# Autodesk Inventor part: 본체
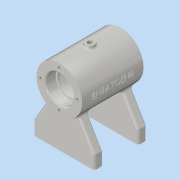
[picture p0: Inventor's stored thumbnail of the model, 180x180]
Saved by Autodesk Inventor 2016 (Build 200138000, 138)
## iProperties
Created: 2018-05
Part Number: 본체
Material: 알루미늄 6061
Document SubType Name: Modeling
Designer: 605-17
Density: 2.7 g/cm^3
Appearance: 알루미늄 - 평지
Mass: 317.791 g
Surface Area: 375.834 cm^2
Volume: 117.701 cm^3
Author: 605-17
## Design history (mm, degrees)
sketch "스케치1"
  geometry: C1 r 26 at (0, 65); 1 further point
  constraints: 1 centre point, 1 vertical alignment
  dimensions: "d0" = 52 diameter of C1; "d1" = 65 distance of point (0, 0) C1.centre
extrude "돌출1" new body sketch "스케치1" stored distance "d2" = 70; taper "d3" = 0 deg
node "작업 평면1"
sketch "스케치3"
  geometry: L1 (-35, 0)-(35, 0); L2 (-35, 0)-(-35, 15); L3 (-35, 15)-(-16.058, 47.808); L4 (-16.058, 47.808)-(16.058, 47.808); L5 (35, 0)-(35, 15); L6 (35, 15)-(16.058, 47.808); 2 further points
  constraints: 12 end point, 2 horizontal, 2 vertical, 1 coincident, 1 midpoint
  dimensions: "d5" = 70 distance of L1.start L1.end; "d6" = 15 distance of L1.start L2.end; "d7" = 30 deg angle of L2 L3; "d8" = 15 distance of L1.end L5.end; "d9" = 30 deg angle of L5 L6; "d10" = 32.11665 distance of L3.end L4.end
extrude "돌출2" join sketch "스케치3" distance "d11" = 10; taper "d12" = 0 deg
sketch "스케치4"
  geometry: L1 (81, 35)-(65, 35); L2 (65, 35)-(65, 23); L3 (65, 23)-(81, 23); L4 (81, 23)-(81, 35); L5 (79, 23)-(65, 23); L6 (65, 23)-(65, 21); L7 (65, 21)-(79, 21); L8 (79, 21)-(79, 23); L9 (86, 21)-(65, 21); L10 (65, 21)-(65, -21); L11 (65, -21)-(86, -21); L12 (86, -21)-(86, 21); L13 (79, -21)-(65, -21); L14 (65, -21)-(65, -23); L15 (65, -23)-(79, -23); L16 (79, -23)-(79, -21); L17 (91, 35)-(39, 35) reference; L18 (81, -23)-(65, -23); L19 (65, -23)-(65, -35); L20 (65, -35)-(81, -35); L21 (81, -35)-(81, -23); 1 further point
  constraints: 40 end point, 10 parallel, 7 collinear, 5 horizontal, 5 perpendicular, 1 midpoint, 1 point on line
  dimensions: "d13" = 12 distance of L1.end L2.end; "d15" = 42 distance of L9.end L10.end; "d16" = 2 distance of L5.end L6.end; "d17" = 2 distance of L13.end L14.end; "d18" = 16 distance of L1.start L1.end; "d19" = 14 distance of L5.start L5.end; "d20" = 21 distance of L9.start L9.end; "d21" = 14 distance of L14.end L15.end; "d22" = 12 distance of L18.end L19.end; "d23" = 16 distance of L19.end L20.end
revolve "회전1" sketch "스케치4" stored, may be unused: angle "d24" = 90 deg
chamfer "모따기1" distance "d25" = 1; stored, may be unused: second distance "d26" = 2, angle "d27" = 45 deg
fillet "모깎기1" dims "d28" = 3
fillet "모깎기2" dims "d29" = 0.3
sketch "스케치5"
  geometry: C1 r 26 at (0, 0) reference; 2 further points
  constraints: 1 vertical alignment
  dimensions: "d30" = 21 distance of C1.centre point (0, 21)
hole "구멍1" sketch "스케치5" at (0, 21) diameter "d31" = 3.242; stored, may be unused: countersink angle "d35" = 90 deg, drill point angle "d37" = 118 deg; dims "d32" = 8, "d33" = 4, "d34" = 2, "d36" = 10
sketch "스케치6"
  geometry: L1 (0, 0)-(70, 0) reference; L2 (0, 0)-(0, 10) reference; 5 further points
  constraints: 1 horizontal, 1 vertical, 3 other
  dimensions: "d41" = 20 horizontal distance of point (35, -20) point (55, 5); "d42" = 25 vertical distance of point (35, -20) point (55, 5); "d45" = 40 distance of point (55, 5) point (15, 5); "d48" = 50 distance of point (55, 5) point (55, -45)
hole "구멍2" sketch "스케치6" at (55, 5), (15, 5), (55, -45), (15, -45) diameter "d51" = 4.134; stored, may be unused: countersink angle "d55" = 90 deg, drill point angle "d57" = 118 deg; dims "d52" = 8, "d53" = 4, "d54" = 2, "d56" = 12.2
node "작업 평면2"
sketch "스케치7"
  geometry: L1 (0, 0)-(91, 0); L2 (91, -35)-(91, 35) reference; L3 (39, -35)-(91, -35) reference; L4 (65, -35)-(65, 35); L5 (82, 35)-(48, 35) reference; 1 further point
  constraints: 4 end point, 3 midpoint, 1 other
  dimensions: "d59" = 35 distance from line of point (65, 0) L5; "d60" = 26 distance from line of L2 point (65, 0)
feature "엠보싱1" sketch "스케치7" dims "d61" = 0.5, "d62" = 0
node "작업 평면3"
sketch "스케치8"
  geometry: C1 r 5 at (0, 0); 1 further point
  constraints: 1 centre point, 1 coincident
  dimensions: "d64" = 10 diameter of C1
extrude "돌출3" join sketch "스케치8" stored distance "d65" = 5; taper "d66" = 0 deg
sketch "스케치9"
  geometry: C1 r 5 at (0, 0) reference; 1 further point
  constraints: 1 coincident
hole "구멍3" sketch "스케치9" at (0, 0) diameter "d67" = 5.188; stored, may be unused: countersink angle "d71" = 90 deg, drill point angle "d73" = 118 deg; dims "d68" = 12, "d69" = 4, "d70" = 2, "d72" = 16
sketch "스케치10"
  geometry: L1 (48, -35)-(82, -35) reference; L2 (63.379, 35)-(66.621, 35) reference; L3 (65, -33.381)-(65, 33.381); 2 further points
  constraints: 2 end point, 1 horizontal alignment, 1 midpoint, 1 vertical
  dimensions: "d75" = 65 distance from line of point (0, 0) L3; "d76" = 66.7623 distance of L3.start L3.end
node "작업 평면6"
  node "작업 평면5"
sketch "스케치11"
  geometry: L1 (-1.619, 26)-(-1.619, -26) reference; C1 r 6 at (33.381, 0); 2 further points
  constraints: 1 centre point, 1 horizontal alignment, 1 midpoint, 1 vertical alignment
  dimensions: "d80" = 12 diameter of C1
extrude "돌출4" join sketch "스케치11" stored distance "d81" = 5; taper "d82" = 0 deg
sketch "스케치12"
  geometry: C1 r 6 at (0, 0) reference; 2 further points
  constraints: 1 coincident
hole "구멍4" sketch "스케치12" at (0, 0) diameter "d83" = 5.188; stored, may be unused: countersink angle "d87" = 90 deg, drill point angle "d89" = 118 deg; dims "d84" = 13, "d85" = 4, "d86" = 2, "d88" = 17
fillet "모깎기3" dims "d90" = 2
fillet "모깎기4" dims "d91" = 3
fillet "모깎기5" dims "d92" = 3
node "솔리드1"
mirror "대칭1"
pattern_circular "원형 패턴1" dims angle "d39" = 360 deg
mirror "대칭2"
node "작업 평면4"
other parameters: "d58" = 63, "d63" = 94, "d77" = 65, "d78" = -20 deg, "d79" = -29
